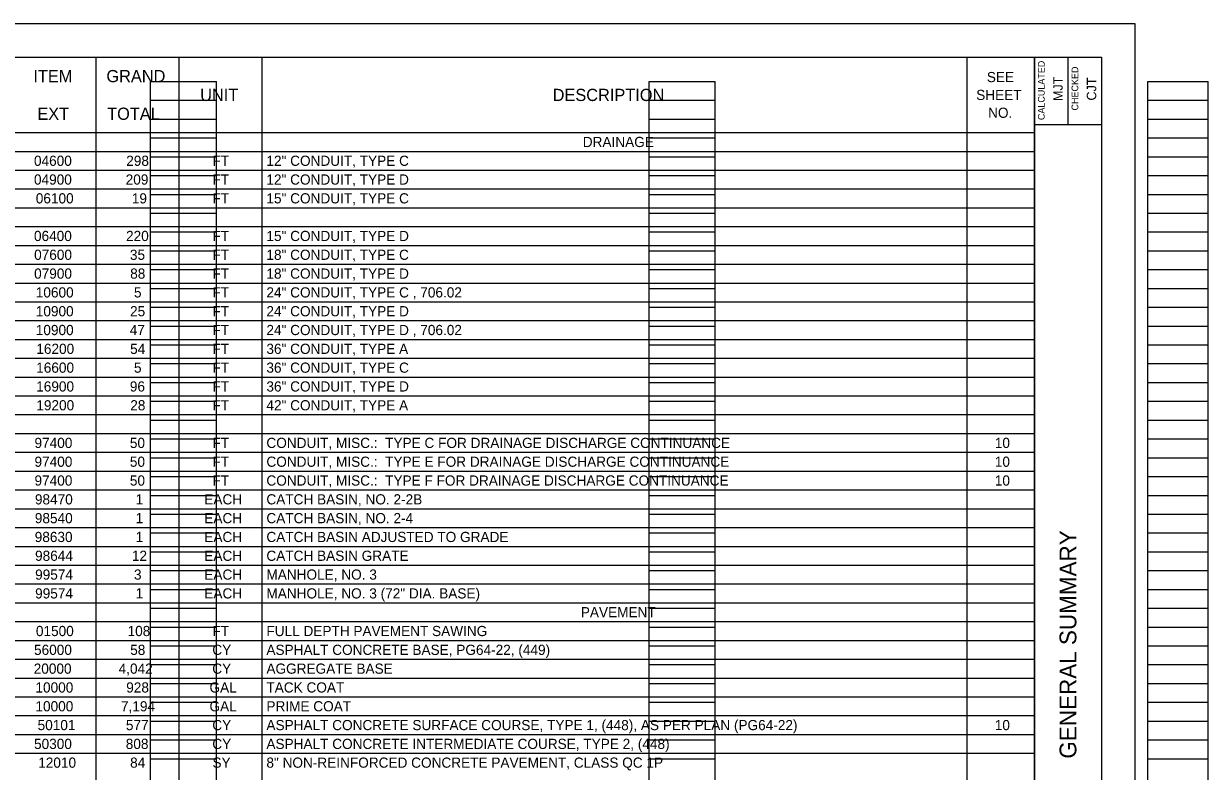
# Model space of a CAD drawing. Extents: x -16 to 102, y -13 to 9.
# Drawn here: x 44.51 to 62.14, y -2.03 to 9.09 of the extents above; entities that cross this region are included whole.
import ezdxf

# ---------------------------------------------------------------- set-up
doc = ezdxf.new("R2010")
doc.units = 0
for name, color, linetype in [('PV_P_EOP', 7, 'Continuous'), ('SH_Border', 7, 'Continuous'), ('SH_Cut_Line', 7, 'Continuous'), ('SH_Data', 7, 'Continuous'), ('TX_P_1', 7, 'Continuous')]:
    doc.layers.add(name, color=color, linetype=linetype)

msp = doc.modelspace()

# ---------------------------------------------------------------- linework, layer by layer
at = {"layer": 'SH_Border'}
for p, q in [((59.554, -12.407), (59.554, 8.593)), ((60.054, 8.593), (60.054, 7.593)), ((59.554, 7.593), (60.554, 7.593))]:
    msp.add_line(p, q, dxfattribs=at)
msp.add_lwpolyline([(29.054, 8.593), (60.554, 8.593), (60.554, -12.407), (29.054, -12.407)], close=True, dxfattribs=at)
at = {"layer": 'SH_Cut_Line'}
msp.add_lwpolyline([(27.054, -12.907), (61.054, -12.907), (61.054, 9.093), (27.054, 9.093)], close=True, dxfattribs=at)
at = {"layer": 'SH_Data'}
for p, q in [((46.402, -11.927), (46.402, 8.233)), ((46.402, 8.233), (47.382, 8.233)), ((47.382, -11.927), (47.382, 8.233)), ((53.822, -11.927), (53.822, 8.233)), ((53.822, 8.233), (54.802, 8.233)), ((54.802, -11.927), (54.802, 8.233)), ((61.242, -11.927), (61.242, 8.233)), ((61.242, 8.233), (62.142, 8.233)), ((62.142, -11.927), (62.142, 8.233)), ((46.402, 7.953), (47.382, 7.953)), ((53.822, 7.953), (54.802, 7.953)), ((61.242, 7.953), (62.142, 7.953)), ((46.402, 7.673), (47.382, 7.673)), ((53.822, 7.673), (54.802, 7.673)), ((61.242, 7.673), (62.142, 7.673)), ((46.402, 7.393), (47.382, 7.393)), ((53.822, 7.393), (54.802, 7.393)), ((61.242, 7.393), (62.142, 7.393)), ((46.402, 7.113), (47.382, 7.113)), ((53.822, 7.113), (54.802, 7.113)), ((61.242, 7.113), (62.142, 7.113)), ((46.402, 6.833), (47.382, 6.833)), ((53.822, 6.833), (54.802, 6.833)), ((61.242, 6.833), (62.142, 6.833)), ((46.402, 6.553), (47.382, 6.553)), ((53.822, 6.553), (54.802, 6.553)), ((61.242, 6.553), (62.142, 6.553)), ((46.402, 6.273), (47.382, 6.273)), ((53.822, 6.273), (54.802, 6.273)), ((61.242, 6.273), (62.142, 6.273)), ((46.402, 5.993), (47.382, 5.993)), ((53.822, 5.993), (54.802, 5.993)), ((61.242, 5.993), (62.142, 5.993)), ((46.402, 5.713), (47.382, 5.713)), ((53.822, 5.713), (54.802, 5.713)), ((61.242, 5.713), (62.142, 5.713)), ((46.402, 5.433), (47.382, 5.433)), ((53.822, 5.433), (54.802, 5.433)), ((61.242, 5.433), (62.142, 5.433)), ((46.402, 5.153), (47.382, 5.153)), ((53.822, 5.153), (54.802, 5.153)), ((61.242, 5.153), (62.142, 5.153)), ((46.402, 4.873), (47.382, 4.873)), ((53.822, 4.873), (54.802, 4.873)), ((61.242, 4.873), (62.142, 4.873)), ((46.402, 4.593), (47.382, 4.593)), ((53.822, 4.593), (54.802, 4.593)), ((61.242, 4.593), (62.142, 4.593)), ((46.402, 4.313), (47.382, 4.313)), ((53.822, 4.313), (54.802, 4.313)), ((61.242, 4.313), (62.142, 4.313)), ((46.402, 4.033), (47.382, 4.033)), ((53.822, 4.033), (54.802, 4.033)), ((61.242, 4.033), (62.142, 4.033)), ((46.402, 3.753), (47.382, 3.753)), ((53.822, 3.753), (54.802, 3.753)), ((61.242, 3.753), (62.142, 3.753)), ((46.402, 3.473), (47.382, 3.473)), ((53.822, 3.473), (54.802, 3.473)), ((61.242, 3.473), (62.142, 3.473)), ((46.402, 3.193), (47.382, 3.193)), ((53.822, 3.193), (54.802, 3.193)), ((61.242, 3.193), (62.142, 3.193)), ((46.402, 2.913), (47.382, 2.913)), ((53.822, 2.913), (54.802, 2.913)), ((61.242, 2.913), (62.142, 2.913)), ((46.402, 2.633), (47.382, 2.633)), ((53.822, 2.633), (54.802, 2.633)), ((61.242, 2.633), (62.142, 2.633)), ((46.402, 2.353), (47.382, 2.353)), ((53.822, 2.353), (54.802, 2.353)), ((61.242, 2.353), (62.142, 2.353)), ((46.402, 2.073), (47.382, 2.073)), ((53.822, 2.073), (54.802, 2.073)), ((61.242, 2.073), (62.142, 2.073)), ((46.402, 1.793), (47.382, 1.793)), ((53.822, 1.793), (54.802, 1.793)), ((61.242, 1.793), (62.142, 1.793)), ((46.402, 1.513), (47.382, 1.513)), ((53.822, 1.513), (54.802, 1.513)), ((61.242, 1.513), (62.142, 1.513)), ((46.402, 1.233), (47.382, 1.233)), ((53.822, 1.233), (54.802, 1.233)), ((61.242, 1.233), (62.142, 1.233)), ((46.402, 0.953), (47.382, 0.953)), ((53.822, 0.953), (54.802, 0.953)), ((61.242, 0.953), (62.142, 0.953)), ((46.402, 0.673), (47.382, 0.673)), ((53.822, 0.673), (54.802, 0.673)), ((61.242, 0.673), (62.142, 0.673)), ((46.402, 0.393), (47.382, 0.393)), ((53.822, 0.393), (54.802, 0.393)), ((61.242, 0.393), (62.142, 0.393)), ((46.402, 0.113), (47.382, 0.113)), ((53.822, 0.113), (54.802, 0.113)), ((61.242, 0.113), (62.142, 0.113)), ((46.402, -0.167), (47.382, -0.167)), ((53.822, -0.167), (54.802, -0.167)), ((61.242, -0.167), (62.142, -0.167)), ((46.402, -0.447), (47.382, -0.447)), ((53.822, -0.447), (54.802, -0.447)), ((61.242, -0.447), (62.142, -0.447)), ((46.402, -0.727), (47.382, -0.727)), ((53.822, -0.727), (54.802, -0.727)), ((61.242, -0.727), (62.142, -0.727)), ((46.402, -1.007), (47.382, -1.007)), ((53.822, -1.007), (54.802, -1.007)), ((61.242, -1.007), (62.142, -1.007)), ((46.402, -1.287), (47.382, -1.287)), ((53.822, -1.287), (54.802, -1.287)), ((61.242, -1.287), (62.142, -1.287)), ((46.402, -1.567), (47.382, -1.567)), ((53.822, -1.567), (54.802, -1.567)), ((61.242, -1.567), (62.142, -1.567)), ((46.402, -1.847), (47.382, -1.847)), ((53.822, -1.847), (54.802, -1.847)), ((61.242, -1.847), (62.142, -1.847))]:
    msp.add_line(p, q, dxfattribs=at)
at = {"layer": 'TX_P_1'}
for p, q in [((29.054, 8.593), (59.554, 8.593)), ((45.589, 8.593), (45.589, -12.405)), ((46.824, 8.593), (46.824, -12.405)), ((48.059, 8.593), (48.059, -12.405)), ((58.549, 8.593), (58.549, -12.405)), ((59.554, 8.593), (59.554, -12.405)), ((29.054, 7.473), (59.554, 7.473)), ((29.054, 7.193), (59.554, 7.193)), ((29.054, 6.913), (59.554, 6.913)), ((29.054, 6.633), (59.554, 6.633)), ((29.054, 6.353), (59.554, 6.353)), ((29.054, 6.073), (59.554, 6.073)), ((29.054, 5.793), (59.554, 5.793)), ((29.054, 5.513), (59.554, 5.513)), ((29.054, 5.233), (59.554, 5.233)), ((29.054, 4.953), (59.554, 4.953)), ((29.054, 4.674), (59.554, 4.674)), ((29.054, 4.394), (59.554, 4.394)), ((29.054, 4.114), (59.554, 4.114)), ((29.054, 3.834), (59.554, 3.834)), ((29.054, 3.554), (59.554, 3.554)), ((29.054, 3.274), (59.554, 3.274)), ((29.054, 2.994), (59.554, 2.994)), ((29.054, 2.714), (59.554, 2.714)), ((29.054, 2.434), (59.554, 2.434)), ((29.054, 2.154), (59.554, 2.154)), ((29.054, 1.874), (59.554, 1.874)), ((29.054, 1.594), (59.554, 1.594)), ((29.054, 1.314), (59.554, 1.314)), ((29.054, 1.034), (59.554, 1.034)), ((29.054, 0.754), (59.554, 0.754)), ((29.054, 0.474), (59.554, 0.474)), ((29.054, 0.194), (59.554, 0.194)), ((29.054, -0.086), (59.554, -0.086)), ((29.054, -0.366), (59.554, -0.366)), ((29.054, -0.646), (59.554, -0.646)), ((29.054, -0.926), (59.554, -0.926)), ((29.054, -1.206), (59.554, -1.206)), ((29.054, -1.486), (59.554, -1.486)), ((29.054, -1.766), (59.554, -1.766))]:
    msp.add_line(p, q, dxfattribs=at)

# ---------------------------------------------------------------- texts
at = {"layer": 'PV_P_EOP'}
for s, p in [('DRAINAGE', (52.833, 7.257)), ('PAVEMENT', (52.804, 0.258))]:
    msp.add_text(s, height=0.1515, dxfattribs=at).set_placement(p)
at = {"layer": 'SH_Data'}
for s, height, p in [('CALCULATED', 0.1, (59.707, 7.658)), ('MJT', 0.14, (59.974, 7.942)), ('CHECKED', 0.1, (60.207, 7.801)), ('CJT', 0.14, (60.474, 7.949)), ('GENERAL SUMMARY', 0.25, (60.179, -1.846))]:
    msp.add_text(s, height=height, rotation=90, dxfattribs=at).set_placement(p)
at = {"layer": 'TX_P_1'}
for s, height, p in [('ITEM', 0.1818, (44.657, 8.222)), ('GRAND', 0.1818, (45.744, 8.222)), ('SEE', 0.1515, (58.846, 8.223)), ('UNIT', 0.1818, (47.139, 7.942)), ('DESCRIPTION', 0.18181, (52.385, 7.942)), ('SHEET', 0.1515, (58.688, 7.957)), ('EXT', 0.1818, (44.716, 7.662)), ('TOTAL', 0.1818, (45.755, 7.662)), ('NO.', 0.1515, (58.865, 7.692)), ('04600', 0.1515, (44.666, 6.977)), ('298', 0.1515, (46.039, 6.977)), ('FT', 0.1515, (47.322, 6.977)), ('12" CONDUIT, TYPE C', 0.15151, (48.125, 6.977)), ('04900', 0.1515, (44.666, 6.698)), ('209', 0.1515, (46.031, 6.698)), ('FT', 0.1515, (47.322, 6.698)), ('12" CONDUIT, TYPE D', 0.15151, (48.125, 6.698)), ('06100', 0.1515, (44.693, 6.418)), ('19', 0.1515, (46.122, 6.418)), ('FT', 0.1515, (47.322, 6.418)), ('15" CONDUIT, TYPE C', 0.15151, (48.125, 6.418)), ('06400', 0.1515, (44.666, 5.858)), ('220', 0.1515, (46.036, 5.858)), ('FT', 0.1515, (47.322, 5.858)), ('15" CONDUIT, TYPE D', 0.15151, (48.125, 5.858)), ('07600', 0.1515, (44.668, 5.578)), ('35', 0.1515, (46.094, 5.578)), ('FT', 0.1515, (47.322, 5.578)), ('18" CONDUIT, TYPE C', 0.15151, (48.125, 5.578)), ('07900', 0.1515, (44.668, 5.298)), ('88', 0.1515, (46.098, 5.298)), ('FT', 0.1515, (47.322, 5.298)), ('18" CONDUIT, TYPE D', 0.15151, (48.125, 5.298)), ('10600', 0.1515, (44.693, 5.018)), ('5', 0.152, (46.154, 5.018)), ('FT', 0.1515, (47.322, 5.018)), ('24" CONDUIT, TYPE C , 706.02', 0.15151, (48.125, 5.018)), ('10900', 0.1515, (44.693, 4.738)), ('25', 0.1515, (46.096, 4.738)), ('FT', 0.1515, (47.322, 4.738)), ('24" CONDUIT, TYPE D', 0.15151, (48.125, 4.738)), ('10900', 0.1515, (44.693, 4.458)), ('47', 0.1515, (46.091, 4.458)), ('FT', 0.1515, (47.322, 4.458)), ('24" CONDUIT, TYPE D , 706.02', 0.15151, (48.125, 4.458)), ('16200', 0.1515, (44.701, 4.178)), ('54', 0.1515, (46.097, 4.178)), ('FT', 0.1515, (47.322, 4.178)), ('36" CONDUIT, TYPE A', 0.15151, (48.125, 4.178)), ('16600', 0.1515, (44.699, 3.898)), ('5', 0.152, (46.154, 3.898)), ('FT', 0.1515, (47.322, 3.898)), ('36" CONDUIT, TYPE C', 0.15151, (48.125, 3.898)), ('16900', 0.1515, (44.699, 3.618)), ('96', 0.1515, (46.093, 3.618)), ('FT', 0.1515, (47.322, 3.618)), ('36" CONDUIT, TYPE D', 0.15151, (48.125, 3.618)), ('19200', 0.1515, (44.701, 3.338)), ('28', 0.1515, (46.099, 3.338)), ('FT', 0.1515, (47.322, 3.338)), ('42" CONDUIT, TYPE A', 0.15151, (48.125, 3.338)), ('97400', 0.1515, (44.674, 2.778)), ('50', 0.1515, (46.093, 2.778)), ('FT', 0.1515, (47.322, 2.778)), ('CONDUIT, MISC.:  TYPE C FOR DRAINAGE DISCHARGE CONTINUANCE', 0.15151, (48.125, 2.778)), ('10', 0.1515, (58.965, 2.778)), ('97400', 0.1515, (44.674, 2.498)), ('50', 0.1515, (46.093, 2.498)), ('FT', 0.1515, (47.322, 2.498)), ('CONDUIT, MISC.:  TYPE E FOR DRAINAGE DISCHARGE CONTINUANCE', 0.15151, (48.125, 2.498)), ('10', 0.1515, (58.965, 2.498)), ('97400', 0.1515, (44.674, 2.218)), ('50', 0.1515, (46.093, 2.218)), ('FT', 0.1515, (47.322, 2.218)), ('CONDUIT, MISC.:  TYPE F FOR DRAINAGE DISCHARGE CONTINUANCE', 0.15151, (48.125, 2.218)), ('10', 0.1515, (58.965, 2.218)), ('98470', 0.1515, (44.68, 1.938)), ('1', 0.152, (46.178, 1.938)), ('EACH', 0.1515, (47.201, 1.938)), ('CATCH BASIN, NO. 2-2B', 0.15151, (48.125, 1.938)), ('98540', 0.1515, (44.679, 1.658)), ('1', 0.152, (46.178, 1.658)), ('EACH', 0.1515, (47.201, 1.658)), ('CATCH BASIN, NO. 2-4', 0.15151, (48.125, 1.658)), ('98630', 0.1515, (44.677, 1.378)), ('1', 0.152, (46.178, 1.378)), ('EACH', 0.1515, (47.201, 1.378)), ('CATCH BASIN ADJUSTED TO GRADE', 0.15151, (48.125, 1.378)), ('98644', 0.1515, (44.682, 1.098)), ('12', 0.1515, (46.123, 1.098)), ('EACH', 0.1515, (47.201, 1.098)), ('CATCH BASIN GRATE', 0.15151, (48.125, 1.098)), ('99574', 0.1515, (44.683, 0.818)), ('3', 0.152, (46.154, 0.818)), ('EACH', 0.1515, (47.201, 0.818)), ('MANHOLE, NO. 3', 0.15151, (48.125, 0.818)), ('99574', 0.1515, (44.683, 0.538)), ('1', 0.152, (46.178, 0.538)), ('EACH', 0.1515, (47.201, 0.538)), ('MANHOLE, NO. 3 (72" DIA. BASE)', 0.15151, (48.125, 0.538)), ('01500', 0.1515, (44.695, -0.022)), ('108', 0.1515, (46.059, -0.022)), ('FT', 0.1515, (47.322, -0.022)), ('FULL DEPTH PAVEMENT SAWING', 0.15151, (48.125, -0.022)), ('56000', 0.1515, (44.667, -0.302)), ('58', 0.1515, (46.098, -0.302)), ('CY', 0.1515, (47.32, -0.302)), ('ASPHALT CONCRETE BASE, PG64-22, (449)', 0.15151, (48.125, -0.302)), ('20000', 0.1515, (44.662, -0.582)), ('4,042', 0.1515, (45.926, -0.582)), ('CY', 0.1515, (47.32, -0.582)), ('AGGREGATE BASE', 0.15151, (48.125, -0.582)), ('10000', 0.1515, (44.688, -0.862)), ('928', 0.1515, (46.039, -0.862)), ('GAL', 0.1515, (47.278, -0.862)), ('TACK COAT', 0.1515, (48.125, -0.862)), ('10000', 0.1515, (44.688, -1.142)), ('7,194', 0.1515, (45.961, -1.142)), ('GAL', 0.1515, (47.278, -1.142)), ('PRIME COAT', 0.1515, (48.125, -1.142)), ('50101', 0.1515, (44.72, -1.422)), ('577', 0.1515, (46.034, -1.422)), ('CY', 0.1515, (47.32, -1.422)), ('ASPHALT CONCRETE SURFACE COURSE, TYPE 1, (448), AS PER PLAN (PG64-22)', 0.15151, (48.125, -1.422)), ('10', 0.1515, (58.965, -1.422)), ('50300', 0.1515, (44.667, -1.702)), ('808', 0.1515, (46.032, -1.702)), ('CY', 0.1515, (47.32, -1.702)), ('ASPHALT CONCRETE INTERMEDIATE COURSE, TYPE 2, (448)', 0.15151, (48.125, -1.702)), ('12010', 0.1515, (44.729, -1.981)), ('84', 0.1515, (46.097, -1.981)), ('SY', 0.1515, (47.322, -1.981)), ('8" NON-REINFORCED CONCRETE PAVEMENT, CLASS QC 1P', 0.15151, (48.125, -1.981))]:
    msp.add_text(s, height=height, dxfattribs=at).set_placement(p)

doc.saveas('drawing.dxf')
